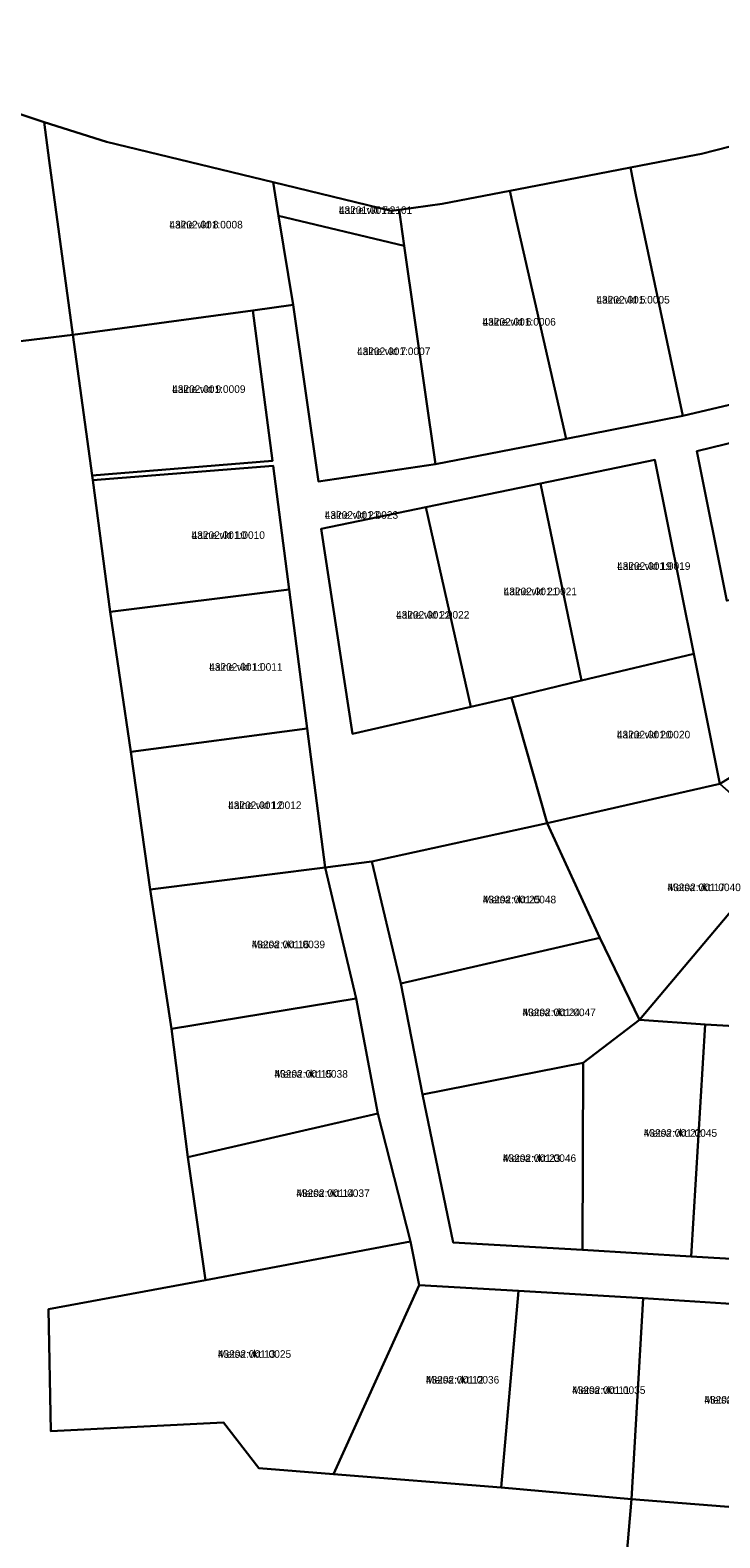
# Model space of a CAD drawing. Extents: x 661852 to 683758, y 6469495 to 6482657.
# Drawn here: x 665448.1 to 665584.5, y 6471214 to 6471512.2 of the extents above; entities that cross this region are included whole.
import ezdxf

# ---------------------------------------------------------------- set-up
doc = ezdxf.new("R2010")
doc.units = 0
for name, color, linetype in [('L_AADRESS', 7, 'Continuous'), ('PIIR', 7, 'Continuous'), ('TUNNUS', 7, 'Continuous')]:
    doc.layers.add(name, color=color, linetype=linetype)

msp = doc.modelspace()

# ---------------------------------------------------------------- linework, layer by layer
at = {"layer": 'PIIR'}
for points in [[(665630.74, 6471514.31), (665625.77, 6471511.37), (665613.96, 6471504.38), (665600.05, 6471496.41), (665597.56, 6471494.98), (665587.44, 6471489.72), (665586.53, 6471489.24), (665580.87, 6471487.8), (665579.86, 6471487.61), (665566.88, 6471485.09), (665550.19, 6471481.86), (665543.02, 6471480.46), (665529.63, 6471477.87), (665521.08, 6471476.73), (665519.55, 6471476.53), (665496.22, 6471482.17), (665463.23, 6471490.15), (665450.93, 6471494.06), (665424.14, 6471502.96)], [(665592.21, 6471367.86), (665584.49, 6471363.17), (665579.35, 6471388.9), (665571.68, 6471427.29), (665549.05, 6471422.6), (665526.36, 6471417.9), (665505.69, 6471413.62), (665511.87, 6471373.06), (665535.3, 6471378.38), (665543.35, 6471380.26), (665550.36, 6471355.42), (665515.72, 6471347.78), (665506.47, 6471346.61), (665502.91, 6471374.13), (665499.36, 6471401.59), (665496.19, 6471426.06), (665460.53, 6471423.23), (665460.38, 6471424.18), (665496.06, 6471427.06), (665492.18, 6471456.82), (665500.14, 6471457.91), (665505.13, 6471422.98), (665528.32, 6471426.42), (665554.1, 6471431.41), (665577.19, 6471435.94), (665602.13, 6471441.82)], [(665412.32, 6471446.67), (665456.55, 6471452), (665460.38, 6471424.18), (665460.53, 6471423.23), (665463.97, 6471397.18), (665468.02, 6471369.48), (665471.87, 6471342.25), (665476.1, 6471314.72), (665479.35, 6471289.34), (665482.78, 6471264.97), (665451.76, 6471259.24), (665452.24, 6471235.11), (665486.35, 6471236.84), (665493.34, 6471227.79), (665508.1, 6471226.6), (665541.27, 6471224.01), (665567.02, 6471221.71), (665560.82, 6471148.88)], [(665605.33, 6471435.17), (665579.99, 6471428.95), (665585.91, 6471399.37)], [(665597.98, 6471351.32), (665584.49, 6471363.17), (665592.21, 6471367.86)], [(665595.91, 6471259.7), (665569.35, 6471261.41), (665544.7, 6471262.89), (665525.07, 6471264), (665523.32, 6471272.67), (665516.92, 6471297.96), (665512.59, 6471320.74), (665506.47, 6471346.61), (665515.72, 6471347.78), (665521.46, 6471323.66), (665525.69, 6471301.75), (665531.76, 6471272.42), (665557.36, 6471270.99), (665578.82, 6471269.7), (665600.27, 6471268.42)]]:
    msp.add_lwpolyline(points, dxfattribs=at)
for points in [[(665451.89, 6471486.45), (665456.55, 6471452), (665412.32, 6471446.67), (665405.94, 6471504.74), (665405.34, 6471509.75), (665424.14, 6471502.96), (665450.93, 6471494.06)], [(665451.89, 6471486.45), (665450.93, 6471494.06), (665463.23, 6471490.15), (665496.22, 6471482.17), (665497.24, 6471475.54), (665500.14, 6471457.91), (665492.18, 6471456.82), (665456.55, 6471452)], [(665567.9, 6471479.65), (665566.88, 6471485.09), (665579.86, 6471487.61), (665580.87, 6471487.8), (665586.53, 6471489.24), (665587.44, 6471489.72), (665588.95, 6471484.26), (665602.13, 6471441.82), (665577.19, 6471435.94)], [(665544.3, 6471474.49), (665543.02, 6471480.46), (665550.19, 6471481.86), (665566.88, 6471485.09), (665567.9, 6471479.65), (665577.19, 6471435.94), (665554.1, 6471431.41)], [(665522.08, 6471469.62), (665497.24, 6471475.54), (665496.22, 6471482.17), (665519.55, 6471476.53), (665521.08, 6471476.73)], [(665522.08, 6471469.62), (665521.08, 6471476.73), (665529.63, 6471477.87), (665543.02, 6471480.46), (665544.3, 6471474.49), (665554.1, 6471431.41), (665528.32, 6471426.42)], [(665497.24, 6471475.54), (665522.08, 6471469.62), (665528.32, 6471426.42), (665505.13, 6471422.98), (665500.14, 6471457.91)], [(665492.18, 6471456.82), (665496.06, 6471427.06), (665460.38, 6471424.18), (665456.55, 6471452)], [(665605.33, 6471435.17), (665616.25, 6471406.48), (665585.91, 6471399.37), (665579.99, 6471428.95)], [(665496.19, 6471426.06), (665499.36, 6471401.59), (665463.97, 6471397.18), (665460.53, 6471423.23)], [(665571.68, 6471427.29), (665579.35, 6471388.9), (665557.19, 6471383.58), (665549.05, 6471422.6)], [(665549.05, 6471422.6), (665557.19, 6471383.58), (665543.35, 6471380.26), (665535.3, 6471378.38), (665526.36, 6471417.9)], [(665526.36, 6471417.9), (665535.3, 6471378.38), (665511.87, 6471373.06), (665505.69, 6471413.62)], [(665499.36, 6471401.59), (665502.91, 6471374.13), (665468.02, 6471369.48), (665463.97, 6471397.18)], [(665557.19, 6471383.58), (665579.35, 6471388.9), (665584.49, 6471363.17), (665550.36, 6471355.42), (665543.35, 6471380.26)], [(665468.02, 6471369.48), (665502.91, 6471374.13), (665506.47, 6471346.61), (665471.87, 6471342.25)], [(665568.64, 6471316.51), (665560.76, 6471332.69), (665550.36, 6471355.42), (665584.49, 6471363.17), (665597.98, 6471351.32)], [(665560.76, 6471332.69), (665521.46, 6471323.66), (665515.72, 6471347.78), (665550.36, 6471355.42)], [(665603.57, 6471314.33), (665581.61, 6471315.6), (665568.64, 6471316.51), (665597.98, 6471351.32), (665621.41, 6471332.54)], [(665506.47, 6471346.61), (665512.59, 6471320.74), (665476.1, 6471314.72), (665471.87, 6471342.25)], [(665568.64, 6471316.51), (665557.52, 6471308.01), (665525.69, 6471301.75), (665521.46, 6471323.66), (665560.76, 6471332.69)], [(665516.92, 6471297.96), (665479.35, 6471289.34), (665476.1, 6471314.72), (665512.59, 6471320.74)], [(665581.61, 6471315.6), (665578.82, 6471269.7), (665557.36, 6471270.99), (665557.52, 6471308.01), (665568.64, 6471316.51)], [(665603.57, 6471314.33), (665600.27, 6471268.42), (665578.82, 6471269.7), (665581.61, 6471315.6)], [(665557.36, 6471270.99), (665531.76, 6471272.42), (665525.69, 6471301.75), (665557.52, 6471308.01)], [(665479.35, 6471289.34), (665516.92, 6471297.96), (665523.32, 6471272.67), (665482.78, 6471264.97)], [(665525.07, 6471264), (665508.1, 6471226.6), (665493.34, 6471227.79), (665486.35, 6471236.84), (665452.24, 6471235.11), (665451.76, 6471259.24), (665482.78, 6471264.97), (665523.32, 6471272.67)], [(665544.7, 6471262.89), (665541.27, 6471224.01), (665508.1, 6471226.6), (665525.07, 6471264)], [(665569.35, 6471261.41), (665567.02, 6471221.71), (665541.27, 6471224.01), (665544.7, 6471262.89)], [(665595.91, 6471259.7), (665592.93, 6471219.62), (665567.02, 6471221.71), (665569.35, 6471261.41)], [(665592.93, 6471219.62), (665601.59, 6471218.91), (665592.24, 6471146.2), (665573.04, 6471147.84), (665560.82, 6471148.88), (665567.02, 6471221.71)]]:
    msp.add_lwpolyline(points, close=True, dxfattribs=at)

# ---------------------------------------------------------------- texts
at = {"layer": 'L_AADRESS'}
for s, p in [('Laine vkt 7a', (665509.19, 6471475.9)), ('Laine vkt 8', (665475.68, 6471473.03)), ('Laine vkt 5', (665560.11, 6471458.18)), ('Laine vkt 6', (665537.59, 6471453.81)), ('Laine vkt 7', (665512.78, 6471447.98)), ('Laine vkt 9', (665476.22, 6471440.5)), ('Laine vkt 23', (665506.4, 6471415.6)), ('Laine vkt 10', (665480.06, 6471411.62)), ('Laine vkt 19', (665564.2, 6471405.5)), ('Laine vkt 21', (665541.77, 6471400.49)), ('Laine vkt 22', (665520.49, 6471395.85)), ('Laine vkt 11', (665483.55, 6471385.54)), ('Laine vkt 20', (665564.16, 6471372.16)), ('Laine vkt 12', (665487.29, 6471358.19)), ('Metsa vkt 17', (665574.17, 6471341.95)), ('Metsa vkt 25', (665537.65, 6471339.54)), ('Metsa vkt 16', (665491.95, 6471330.66)), ('Metsa vkt 24', (665545.5, 6471317.22)), ('Metsa vkt 15', (665496.46, 6471305.04)), ('Metsa vkt 22', (665569.48, 6471293.36)), ('Metsa vkt 23', (665541.61, 6471288.38)), ('Metsa vkt 14', (665500.78, 6471281.46)), ('Metsa vkt 13', (665485.25, 6471249.64)), ('Metsa vkt 12', (665526.4, 6471244.55)), ('Metsa vkt 11', (665555.31, 6471242.5)), ('Metsa vkt 10', (665581.46, 6471240.59))]:
    msp.add_text(s, height=1.5, dxfattribs=at).set_placement(p)
at = {"layer": 'TUNNUS'}
for s, p in [('43201:001:2101', (665509.19, 6471475.9)), ('43202:001:0008', (665475.68, 6471473.03)), ('43202:001:0005', (665560.11, 6471458.18)), ('43202:001:0006', (665537.59, 6471453.81)), ('43202:001:0007', (665512.78, 6471447.98)), ('43202:001:0009', (665476.22, 6471440.5)), ('43202:001:0023', (665506.4, 6471415.6)), ('43202:001:0010', (665480.06, 6471411.62)), ('43202:001:0019', (665564.2, 6471405.5)), ('43202:001:0021', (665541.77, 6471400.49)), ('43202:001:0022', (665520.49, 6471395.85)), ('43202:001:0011', (665483.55, 6471385.54)), ('43202:001:0020', (665564.16, 6471372.16)), ('43202:001:0012', (665487.29, 6471358.19)), ('43202:001:0040', (665574.17, 6471341.95)), ('43202:001:0048', (665537.65, 6471339.54)), ('43202:001:0039', (665491.95, 6471330.66)), ('43202:001:0047', (665545.5, 6471317.22)), ('43202:001:0038', (665496.46, 6471305.04)), ('43202:001:0045', (665569.48, 6471293.36)), ('43202:001:0046', (665541.61, 6471288.38)), ('43202:001:0037', (665500.78, 6471281.46)), ('43202:001:0025', (665485.25, 6471249.64)), ('43202:001:0036', (665526.4, 6471244.55)), ('43202:001:0035', (665555.31, 6471242.5)), ('43202:001:0034', (665581.46, 6471240.59))]:
    msp.add_text(s, height=1.5, dxfattribs=at).set_placement(p)

doc.saveas('drawing.dxf')
